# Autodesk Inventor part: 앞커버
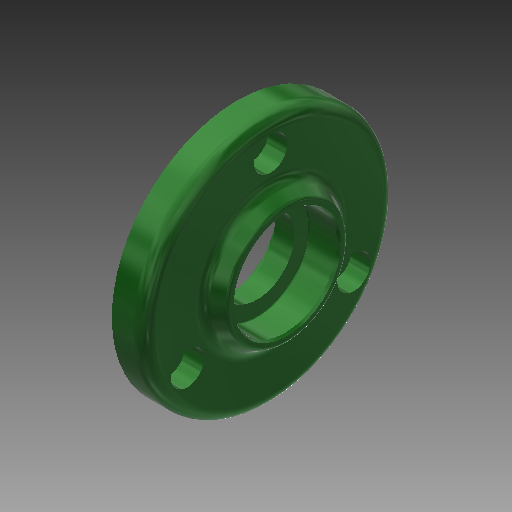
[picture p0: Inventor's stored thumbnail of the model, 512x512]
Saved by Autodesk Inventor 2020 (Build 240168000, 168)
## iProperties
Created: 2015-11
Part Number: 앞커버
Material: 알루미늄 6061
Document SubType Name: Modeling
Designer: mduedu
Density: 1 g/cm^3
Appearance: 매끄러움 - 짙은 산림 녹색
Author: mduedu
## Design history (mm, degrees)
sketch "스케치5"
  geometry: C1 r 30 at (0, 0); 2 further points
  constraints: 2 coincident, 1 centre point
  dimensions: "d66" = 60 diameter of C1
extrude "돌출2" new body sketch "스케치5" distance "d67" = 8; taper "d68" = 0 deg
sketch "스케치9"
  geometry: C1 r 16.5 at (0, 0); 1 further point
  constraints: 1 centre point, 1 coincident
  dimensions: "d146" = 33 diameter of C1
extrude "돌출4" join sketch "스케치9" distance "d147" = 4; taper "d148" = -30 deg
sketch "스케치6"
  geometry: C1 r 16 at (0, 0); 1 further point
  constraints: 1 centre point, 1 coincident
  dimensions: "d69" = 32 diameter of C1
extrude "돌출3" join sketch "스케치6" distance "d70" = 3; taper "d71" = 0 deg
hole "구멍7" diameter "d98" = 25; stored, may be unused: countersink angle "d102" = 90 deg, drill point angle "d104" = 0 deg; dims "d96" = 10, "d97" = 10, "d99" = 6, "d100" = 4, "d101" = 2, "d103" = 3
hole "구멍8" diameter "d107" = 25; stored, may be unused: countersink angle "d111" = 90 deg, drill point angle "d113" = 0 deg; dims "d108" = 6, "d109" = 4, "d110" = 2, "d112" = 7.3, "d151" = 10, "d152" = 10
hole "구멍9" diameter "d116" = 18; stored, may be unused: countersink angle "d120" = 90 deg, drill point angle "d122" = 0 deg; dims "d117" = 6, "d118" = 4, "d119" = 2, "d121" = 7.7, "d154" = 10, "d155" = 10
chamfer "모따기2" distance "d123" = 0.6; stored, may be unused: second distance "d124" = 2, angle "d125" = 30 deg
fillet "모깎기11" dims "d126" = 0.3
fillet "모깎기13" dims "d128" = 3
fillet "모깎기14" dims "d129" = 3
fillet "모깎기15" dims "d130" = 0.3
sketch "스케치8" dims "d131" = 46
  geometry: 3 further points
  constraints: 2 vertical alignment, 1 coincident, 2 other
hole "구멍10" sketch "스케치8" at (0, 23) diameter "d132" = 4.5; stored, may be unused: countersink angle "d136" = 90 deg, drill point angle "d138" = 0 deg; dims "d133" = 6, "d134" = 8, "d135" = 4.6, "d137" = 7.7
chamfer "모따기3" distance "d143" = 1; stored, may be unused: second distance "d144" = 2, angle "d145" = 45 deg
fillet "모깎기16" dims "d149" = 1
node "솔리드2"
pattern_circular "원형 패턴4" dims angle "d140" = 360 deg
